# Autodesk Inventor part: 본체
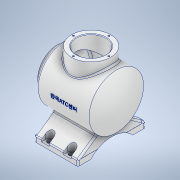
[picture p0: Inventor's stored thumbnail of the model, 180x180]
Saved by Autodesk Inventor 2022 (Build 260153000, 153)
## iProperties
Created: 2023-04
Part Number: 본체
Material: 알루미늄 6061
Document SubType Name: Modeling
Designer: Admin
Mass: 1268.09 g
Surface Area: 1064.58 cm^2
Volume: 469.663 cm^3
Density: 2.7 g/cm^3
Appearance: 알루미늄 - 평지
Author: Admin
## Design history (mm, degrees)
sketch "스케치1"
  geometry: L1 (-78.235, 0)-(97.232, 0) reference; L2 (0, -29.127)-(0, 63.971) reference; L3 (-48.168, 50)-(48.168, 50); L4 (48.168, 50)-(48.168, 0); L5 (-48.168, 0)-(-48.168, 50); L6 (-48.168, 0)-(72.165, 0); A1 r 113 centre (-53.168, 0) between (59.832, 0) and (48.168, 50); 3 further points
  constraints: 8 end point, 5 point on line, 3 point on circle, 1 centre point, 1 collinear, 1 horizontal, 1 parallel, 1 perpendicular, 1 other
  dimensions: "d2" = 100 diameter of L3 L1; "d3" = 23.99706 distance from line of L6.end L4; "d5" = 113 radius of A1; "d16" = 108 distance from line of A1.start L5
revolve "회전1" sketch "스케치1" stored, may be unused: angle "d4" = 360 deg
sketch "스케치2"
  geometry: L1 (0, -70)-(0, 70) reference; L2 (-70, 0)-(70, 0) reference; C1 r 36 at (0, 0); 1 further point
  constraints: 1 centre point, 1 coincident
  dimensions: "d7" = 72 diameter of C1
extrude "돌출1" join sketch "스케치2" distance "d8" = 12; taper "d9" = 0 deg
node "작업 평면1"
sketch "스케치3"
  geometry: L1 (81.835, 0)-(-69.835, 0) reference; L2 (0, -86.8)-(0, 86.8) reference; L3 (60.168, -36)-(60.168, 36) reference; L4 (48.168, 36)-(48.168, -36) reference; L5 (48.168, 50)-(48.168, -50) reference; L6 (-48.168, 50)-(-48.168, -50) reference; L7 (-48.168, 50)-(-48.168, -50) reference; L8 (40.168, -62)-(-39.832, -62); L9 (-39.832, -62)-(-39.832, 62); L10 (-39.832, 62)-(40.168, 62); L11 (40.168, 62)-(40.168, -62); L12 (40.168, -62)-(-39.832, 62); L13 (-39.832, -62)-(40.168, 62); 2 further points
  constraints: 12 end point, 2 midpoint, 2 parallel, 1 horizontal, 1 perpendicular, 1 point on line
  dimensions: "d11" = 80 distance of L8.start L8.end; "d12" = 124 distance of L8.end L9.end; "d13" = 20 distance between parallel lines of L3 L11
extrude "돌출2" join sketch "스케치3" distance "d14" = 10; taper "d15" = 0 deg
sketch "스케치4"
  geometry: L1 (-67, 62)-(-42.278, 26.694); L2 (-77, 62)-(-67, 62) reference; L3 (-77, -62)-(-67, -62) reference; L4 (-67, 62)-(-67, -62) reference; L5 (-67, -62)-(-42.278, -26.694); L6 (0, -86.8)-(0, 86.8) reference; L7 (-102.4, 0)-(75.4, 0) reference; L8 (-67, -62)-(-67, 62); C1 r 36 at (0, 0) reference; C2 r 36 at (0, 0) reference; C3 r 50 at (0, 0); A1 r 50 centre (0, 0) between (-42.278, 26.694) and (-42.278, -26.694) reference; A2 r 50 centre (0, 0) between (-42.278, 26.694) and (-42.278, -26.694) reference; 3 further points
  constraints: 6 end point, 2 point on circle, 1 centre point, 1 coincident, 1 perpendicular
  dimensions: "d17" = 55 deg angle of L2 L1; "d19" = 55 deg angle of L3 L5; "d20" = 100 diameter of C3
extrude "돌출3" join sketch "스케치4" stored distance "d21" = 80; taper "d22" = 0 deg
sketch "스케치5"
  geometry: L1 (62, -61.725)-(62, 158.454) reference; L2 (-24.8, 77)-(148.8, 77) reference; L3 (124, 0)-(0, 0) reference; L4 (0, 0)-(0, 10) reference; L5 (23.5, 0)-(100.5, 0); L6 (62, 17)-(73.395, 17); A1 r 52.096 centre (62, -35.096) between (100.5, 0) and (23.5, 0); 1 further point
  constraints: 4 end point, 3 point on circle, 2 point on line, 1 centre point, 1 collinear, 1 horizontal, 1 tangent, 1 other
  dimensions: "d23" = 77 distance of L5.start L5.end; "d24" = 23.5 distance from line of L5.start L4; "d117" = 17 distance from line of L3 L6.start
extrude "돌출4" cut sketch "스케치5" extent not by distance; stored distance "d26" = 80; taper "d27" = 0 deg
node "작업 평면2"
sketch "스케치6"
  geometry: L1 (79.768, 0)-(-57.432, 0) reference; L2 (0, -50.4)-(0, 50.4) reference; L3 (60.168, -36)-(60.168, 36) reference; C1 r 36 at (-1.832, 0); 1 further point
  constraints: 1 centre point, 1 point on line
  dimensions: "d32" = 72 diameter of C1; "d33" = 62 distance from line of L3 C1.centre
extrude "돌출5" join sketch "스케치6" stored distance "d34" = 10; taper "d35" = 0 deg
sketch "스케치7"
  geometry: L1 (-86, 0)-(82, 0) reference; L2 (-62, 36)-(-62, -36) reference; L3 (38, 62)-(-41.832, 62) reference; C1 r 27 at (0, 0); 1 further point
  constraints: 1 centre point
  dimensions: "d36" = 54 diameter of C1; "d37" = 62 distance from line of L2 C1.centre; "d38" = 62 distance from line of L3 C1.centre
sketch "스케치8"
  geometry: C1 r 27 at (0, 0); 1 further point
  constraints: 1 centre point, 1 coincident
  dimensions: "d39" = 54 diameter of C1
extrude "돌출6" cut sketch "스케치8" distance "d40" = 19; taper "d41" = 0 deg
sketch "스케치9"
  geometry: L1 (-41.168, -27)-(-41.168, 27) reference; L2 (-41.168, 0)-(45.331, 0); L3 (45.331, 0)-(45.331, 43); L4 (45.331, 43)-(-41.168, 43); L5 (-41.168, 43)-(-41.168, 0); L6 (-84.168, 0)-(83.832, 0) reference; L7 (0, -70)-(0, 70) reference; L8 (53.832, 0)-(45.331, 0); L9 (-60.168, -27)-(-60.168, 27) reference; L10 (53.832, 0)-(45.331, 0); L11 (53.832, 0)-(45.331, 0); L12 (48.168, -50)-(48.168, 50) reference; A1 r 113 centre (-59.168, 0) between (53.832, 0) and (45.331, 43); A2 r 113 centre (-53.168, 0) between (48.168, -50) and (48.168, 50) reference; 2 further points
  constraints: 14 end point, 3 point on circle, 3 point on line, 2 collinear, 2 parallel, 2 perpendicular, 1 centre point, 1 horizontal, 1 midpoint
  dimensions: "d42" = 86 diameter of L4 L6; "d44" = 113 radius of A1; "d45" = 114 distance from line of L9 L8.start
revolve "회전2" sketch "스케치9" stored, may be unused: angle "d46" = 90 deg
sketch "스케치10"
  geometry: 1 further point
extrude "돌출7" cut sketch "스케치7" stored distance "d47" = 19; taper "d48" = 0 deg
sketch "스케치11"
  geometry: L1 (-86, 0)-(82, 0) reference; L2 (38, 62)-(-41.832, 62) reference; L3 (-62, 36)-(-62, -36) reference; A1 r 32.5 centre (0, 0) between (32.5, 0) and (0, -32.5); 3 further points
  constraints: 4 point on circle, 2 point on line, 1 centre point
  dimensions: "d49" = 65 diameter of A1; "d50" = 62 distance from line of L2 A1.centre; "d51" = 62 distance from line of L3 A1.centre
hole "구멍1" sketch "스케치11" at (32.5, 0), (0, -32.5), (-32.5, 0), (0.249, 32.499) diameter "d52" = 3.242; stored, may be unused: countersink angle "d56" = 90 deg, drill point angle "d58" = 118 deg; dims "d53" = 8, "d54" = 4, "d55" = 2, "d57" = 10
sketch "스케치14"
  geometry: L1 (0, -70)-(0, 70) reference; L2 (-70, 0)-(70, 0) reference; A1 r 32.5 centre (0, 0) between (0, 32.5) and (32.5, 0); 3 further points
  constraints: 4 point on circle, 4 point on line, 1 centre point, 1 coincident
  dimensions: "d59" = 65 diameter of A1
hole "구멍2" sketch "스케치14" at (0, 32.5), (32.5, 0), (0, -32.5), (-32.5, 0) diameter "d60" = 3.242; stored, may be unused: countersink angle "d64" = 90 deg, drill point angle "d66" = 118 deg; dims "d61" = 8, "d62" = 4, "d63" = 2, "d65" = 10
sketch "스케치15"
  geometry: L1 (39.832, 62)-(39.832, 38.5) reference; L2 (-40.168, 62)-(39.832, 62) reference; L3 (39.832, -38.5)-(39.832, -62) reference; L4 (39.832, -62)-(-40.168, -62) reference; 5 further points
  dimensions: "d67" = 20 distance from line of L1 point (19.832, 54); "d68" = 8 distance from line of L2 point (19.832, 54); "d69" = 40 distance of point (19.832, 54) point (-20.168, 54); "d70" = 8 distance from line of L2 point (-20.168, 54); "d71" = 20 distance from line of L3 point (19.832, -54); "d72" = 8 distance from line of L4 point (19.832, -54); "d73" = 8 distance from line of L4 point (-20.168, -54); "d74" = 40 distance of point (19.832, -54) point (-20.168, -54)
sketch "스케치16"
  geometry: 1 further point
hole "구멍3" sketch "스케치15" diameter "d75" = 9; stored, may be unused: countersink angle "d79" = 90 deg, drill point angle "d81" = 0 deg; dims "d76" = 40 (= d74), "d77" = 4, "d78" = 2, "d80" = 6
sketch "스케치21"
  geometry: L1 (60, -8)-(-20, -8) reference; L2 (-20, -8)-(-20, 15.5) reference; 2 further points
  dimensions: "d97" = 8 distance from line of L1 point (0, 0); "d98" = 20 distance from line of L2 point (0, 0)
hole "구멍4" sketch "스케치21" at (0, 0) diameter "d99" = 14; stored, may be unused: countersink angle "d103" = 90 deg, drill point angle "d105" = 0 deg; dims "d100" = 6, "d101" = 4, "d102" = 2, "d104" = 16
node "작업 평면3"
sketch "스케치22"
  geometry: L1 (-60.168, 36)-(-60.168, -36) reference; L2 (37.832, 65)-(-34.168, 65) reference; L3 (-40.168, -77)-(39.832, -77) reference; 2 further points
  constraints: 1 other
  dimensions: "d106" = 62 distance from line of L1 point (1.832, 0); "d108" = 77 distance from line of L3 point (1.832, 0)
feature "엠보싱1" sketch "스케치22" dims "d109" = 0.5, "d110" = 0
fillet "모깎기1" dims "d111" = 3
chamfer "모따기1" distance "d112" = 1; stored, may be unused: second distance "d113" = 2, angle "d114" = 45 deg
fillet "모깎기3" dims "d116" = 2
fillet "모깎기4" dims "d118" = 3
sketch "스케치23" dims "d121" = 14
  geometry: L1 (-17, -8)-(57, -8) reference; L2 (-7, 0)-(-7, -8); L3 (-17, -8)-(57, -8) reference; L4 (-20, 15.5)-(-20, -5) reference; L5 (-20, 15.5)-(60, 15.5) reference; L6 (60, -5)-(60, 15.5) reference; L7 (-17, -8)-(57, -8) reference; L8 (7, 0)-(7, -8); L9 (7, -8)-(7, 0); L10 (-7, -8)-(7, -8); C1 r 4.5 at (40, 0) reference; C2 r 4.5 at (0, 0) reference; A1 r 7 centre (0, 0) between (0, -7) and (-1.957, -6.721) reference; A2 r 3 centre (-17, -5) between (-20, -5) and (-17, -8) reference; A3 r 3 centre (57, -5) between (57, -8) and (60, -5) reference; 3 further points
  constraints: 8 end point, 2 collinear, 2 perpendicular, 2 point on line, 1 coincident, 1 point on circle, 3 other
  dimensions: "d119" = 8 distance of L2.start L2.end; "d120" = 8 distance of L8.start L8.end
extrude "돌출9" cut sketch "스케치23" distance "d122" = 10; taper "d123" = 0 deg
node "솔리드1"
mirror "미러2"
mirror "미러3"
mirror "미러4"
mirror "미러5"
node "투영된 루프1"
node "투영된 루프2"
node "투영된 루프3"
node "투영된 루프4"
node "투영된 루프5"
feature "A9D066F2-1C7D-4E18-AEED-F7BC21143FA4" dims "d75" = 9, "d76" = 40 (= d74), "d77" = 4, "d78" = 2, "d79" = 90 deg, "d80" = 6, "d81" = 0
other parameters: "d10" = -77, "d31" = 65
